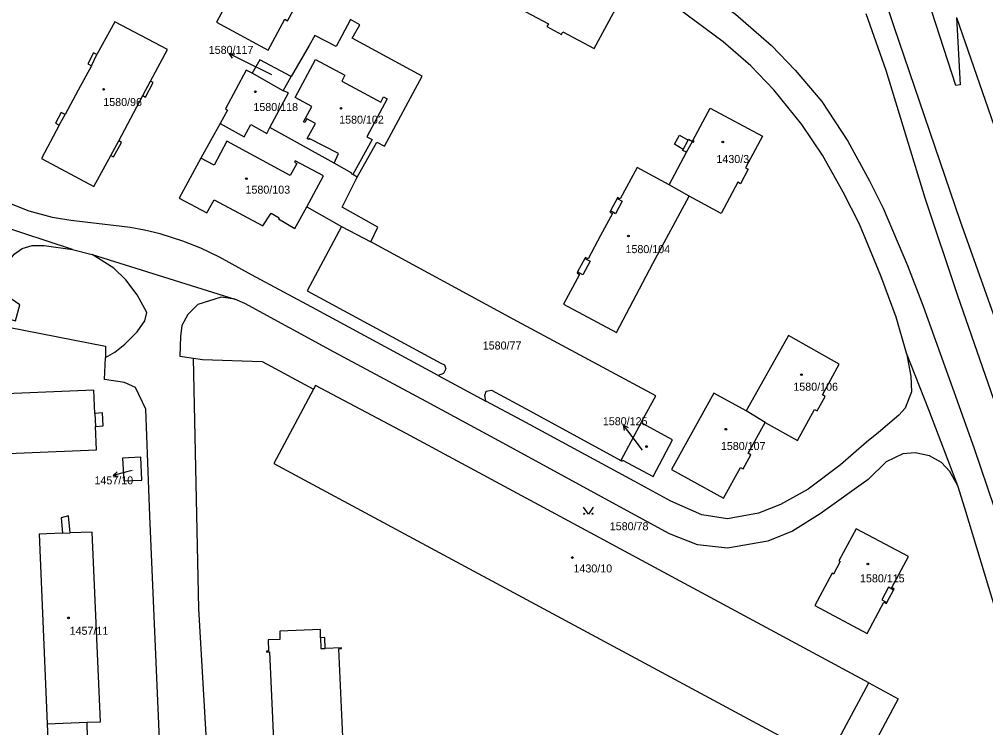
# Model space of a CAD drawing. Extents: x -737240 to -735272, y -1119606 to -1117878.
# Drawn here: x -736070.6 to -735865.3, y -1118481.5 to -1118331.1 of the extents above; entities that cross this region are included whole.
import ezdxf

# ---------------------------------------------------------------- set-up
doc = ezdxf.new("R2010")
doc.units = 0
for name, color, linetype in [('Level 1', 7, 'Continuous'), ('Level 16', 7, 'Continuous'), ('Level 18', 7, 'Continuous'), ('Level 19', 7, 'Continuous'), ('Level 25', 7, 'Continuous'), ('Level 4', 7, 'Continuous')]:
    doc.layers.add(name, color=color, linetype=linetype)

msp = doc.modelspace()

# ---------------------------------------------------------------- linework, layer by layer
at = {"layer": 'Level 1'}
for p, q in [((-735871.5, -1118330.76), (-735863.57, -1118353.56)), ((-736014.55, -1118346.3), (-736021.15, -1118342.55)), ((-736014.55, -1118346.3), (-736012.85, -1118343.25)), ((-736027.93, -1118353.21), (-736032.05, -1118360.56)), ((-736003.75, -1118361.65), (-736017.37, -1118354.1)), ((-735932.57, -1118366.22), (-735928.88, -1118359.35)), ((-735998.8, -1118364.6), (-735999.77, -1118364.06)), ((-735928.33, -1118368.63), (-735932.57, -1118366.22)), ((-735943.62, -1118369.13), (-735945.03, -1118371.81)), ((-736009.55, -1118370.95), (-736002.16, -1118375.09)), ((-736059.31, -1118379.99), (-736081.16, -1118372.84)), ((-736002.16, -1118375.09), (-735995.92, -1118378.38)), ((-736059.31, -1118379.99), (-736055.13, -1118381.03)), ((-736055.13, -1118381.03), (-736024.84, -1118390.55)), ((-735950.45, -1118381.87), (-735951.99, -1118384.74)), ((-735981.63, -1118406.73), (-735971.52, -1118412.19)), ((-735912.15, -1118416.72), (-735916.21, -1118414.23)), ((-735938.42, -1118416.56), (-735942.8, -1118424.77)), ((-735886.28, -1118454.95), (-735884.86, -1118452.29))]:
    msp.add_line(p, q, dxfattribs=at)
for points in [[(-736132.41, -1118173.31), (-735949.71, -1118307.16), (-735930.63, -1118321.15), (-735918.49, -1118330.04), (-735910.8, -1118336.7), (-735905.76, -1118341.88), (-735900.15, -1118348.58), (-735894.58, -1118356.95), (-735890.02, -1118365.43), (-735887.12, -1118371.18), (-735881.94, -1118383.37), (-735878.62, -1118392.03), (-735872.34, -1118409.36), (-735867.8, -1118422.01), (-735863.53, -1118434.8)], [(-735882.16, -1118401.98), (-735884.31, -1118394.32), (-735887.57, -1118385.55), (-735892.14, -1118374.64), (-735895.59, -1118367.84), (-735899.94, -1118359.98), (-735904.37, -1118353.42), (-735910.3, -1118346.1), (-735915.18, -1118341), (-735921.08, -1118335.86), (-735934.46, -1118325.93), (-735953.53, -1118311.86), (-735987.19, -1118287.78), (-736042.03, -1118247.22)], [(-735963.03, -1118329.52), (-735958.22, -1118332.09), (-735958.53, -1118332.66), (-735955.44, -1118334.31), (-735955.14, -1118333.74), (-735948.48, -1118337.3), (-735942.52, -1118326.26), (-735949.37, -1118322.57), (-735949.51, -1118322.82), (-735952.2, -1118321.36), (-735952.07, -1118321.11), (-735957.07, -1118318.42), (-735962.08, -1118315.73), (-735962.21, -1118315.97), (-735964.86, -1118314.54), (-735964.73, -1118314.3), (-735971.6, -1118310.59), (-735977.6, -1118321.72), (-735970.93, -1118325.29), (-735971.25, -1118325.88), (-735968.16, -1118327.53), (-735967.84, -1118326.94), (-735963.03, -1118329.52)], [(-736024.98, -1118324.72), (-736028.73, -1118331.75), (-736017.77, -1118337.69), (-736014.2, -1118331.09)], [(-736014.2, -1118331.09), (-736013.61, -1118331.41), (-736011.95, -1118328.34), (-736012.51, -1118328.04)], [(-735890.77, -1118329.85), (-735886.52, -1118341.93), (-735878.2, -1118368.98), (-735871.31, -1118389.76), (-735858.97, -1118425.18), (-735845.83, -1118463.37)], [(-736042.72, -1118344.22), (-736039.16, -1118337.53), (-736050.34, -1118331.61), (-736054.14, -1118338.61)], [(-735998.8, -1118364.6), (-735994.62, -1118357.18), (-735993.05, -1118358.05), (-735985, -1118343.15), (-735999.87, -1118335.12), (-735998.28, -1118332.29), (-736000.23, -1118331.14), (-736003.3, -1118336.9), (-736007.84, -1118334.58), (-736009.02, -1118336.69), (-736012.85, -1118343.25)], [(-736054.14, -1118338.61), (-736054.82, -1118338.24), (-736056.07, -1118340.55), (-736055.28, -1118340.98)], [(-736012.85, -1118343.25), (-736019.5, -1118339.7), (-736021.15, -1118342.55)], [(-736055.28, -1118340.98), (-736058.09, -1118346.17), (-736060.88, -1118351.32)], [(-736021.15, -1118342.55), (-736022.39, -1118341.92), (-736026.83, -1118350.15), (-736026.35, -1118350.4), (-736027.93, -1118353.21)], [(-736044.37, -1118347.31), (-736043.8, -1118347.62), (-736042.15, -1118344.52), (-736042.72, -1118344.22)], [(-736017.37, -1118354.1), (-736013.45, -1118346.74), (-736014.55, -1118346.3)], [(-736049.5, -1118356.94), (-736046.93, -1118352.11), (-736044.37, -1118347.31)], [(-735927.62, -1118357.03), (-735927.36, -1118357.17), (-735927.26, -1118356.99), (-735927.53, -1118356.85), (-735923.83, -1118349.99), (-735912.73, -1118355.93), (-735916.3, -1118362.62), (-735915.74, -1118362.92), (-735917.39, -1118366.01), (-735917.96, -1118365.71), (-735921.51, -1118372.36), (-735928.33, -1118368.63)], [(-736060.88, -1118351.32), (-736061.7, -1118350.87), (-736062.91, -1118353.18), (-736062.11, -1118353.62)], [(-736062.11, -1118353.62), (-736065.9, -1118360.63), (-736054.75, -1118366.64), (-736051.15, -1118360.04)], [(-736027.93, -1118353.21), (-736022.86, -1118356.06), (-736021.39, -1118353.44), (-736018.03, -1118355.32), (-736017.37, -1118354.1)], [(-735929.58, -1118358.75), (-735931.43, -1118357.61), (-735930.39, -1118355.72), (-735928.5, -1118356.74)], [(-735928.5, -1118356.74), (-735928.42, -1118356.59), (-735927.62, -1118357.03)], [(-736051.15, -1118360.04), (-736050.58, -1118360.34), (-736048.93, -1118357.25), (-736049.5, -1118356.94)], [(-735928.88, -1118359.35), (-735929.67, -1118358.93), (-735929.58, -1118358.75)], [(-736032.05, -1118360.56), (-736036.68, -1118369.1), (-736030.75, -1118372.23), (-736029.23, -1118369.42), (-736018.86, -1118374.99), (-736017.09, -1118372.24), (-736015.39, -1118373.23), (-736015.53, -1118373.48), (-736012.05, -1118375.5), (-736009.55, -1118370.95)], [(-735999.77, -1118364.06), (-736000.05, -1118363.9), (-735999.97, -1118363.76), (-736003.75, -1118361.65)], [(-735932.57, -1118366.22), (-735939.34, -1118362.57), (-735942.93, -1118369.22), (-735943.5, -1118368.91), (-735943.62, -1118369.13)], [(-735995.92, -1118378.38), (-735994.45, -1118375.26), (-736001.99, -1118370.98), (-735998.8, -1118364.6)], [(-735951.99, -1118384.74), (-735952.12, -1118384.97), (-735951.57, -1118385.26), (-735954.98, -1118391.58), (-735943.77, -1118397.62), (-735936, -1118382.98), (-735928.33, -1118368.63)], [(-736210.35, -1118369.86), (-736124.09, -1118377.65), (-736118.86, -1118378.12), (-736090.36, -1118393.09), (-736052.32, -1118400.48), (-736052.29, -1118402.89)], [(-735981.63, -1118406.73), (-736007.57, -1118392.76), (-736021.29, -1118385.4), (-736028.1, -1118381.59), (-736032.04, -1118379.73), (-736035.9, -1118378.2), (-736040.7, -1118376.65), (-736044.01, -1118375.88), (-736047.06, -1118375.3), (-736050.57, -1118374.86), (-736059.63, -1118373.8), (-736063.58, -1118373.19), (-736068.55, -1118371.85), (-736072.64, -1118370.2)], [(-735945.03, -1118371.81), (-735945.15, -1118372.03), (-735944.6, -1118372.33), (-735947.11, -1118376.99), (-735949.78, -1118381.95), (-735950.33, -1118381.65), (-735950.45, -1118381.87)], [(-736002.16, -1118375.09), (-736009.45, -1118388.75), (-735981.08, -1118404.09), (-735980.26, -1118404.51), (-735979.97, -1118405.34), (-735980.5, -1118406.29), (-735981.63, -1118406.73)], [(-736088.43, -1118390.14), (-736071.45, -1118395.11), (-736070.47, -1118391.75), (-736072.34, -1118390.47), (-736073.5, -1118388.55), (-736073.92, -1118386.61), (-736073.71, -1118384.56), (-736072.98, -1118382.66), (-736071.67, -1118380.97), (-736070.03, -1118379.76), (-736067.91, -1118379.12), (-736065.33, -1118379.12), (-736059.31, -1118379.99)], [(-735938.42, -1118416.56), (-735935.38, -1118411.03), (-735965.68, -1118394.77), (-735995.92, -1118378.38)], [(-736052.29, -1118402.89), (-736050.29, -1118401.81), (-736048.17, -1118400.11), (-736045.58, -1118397.49), (-736043.97, -1118395.14), (-736043.55, -1118393.33), (-736045.54, -1118389.63), (-736048, -1118386.46), (-736050.54, -1118383.93), (-736055.13, -1118381.03)], [(-736024.84, -1118390.55), (-736027.76, -1118390.11), (-736032.71, -1118391.67), (-736034.82, -1118393.76), (-736036.07, -1118396.14), (-736036.38, -1118398.46), (-736036.53, -1118402.65), (-736033.57, -1118403.05)], [(-735871.23, -1118430.17), (-735872.91, -1118427.1), (-735874.66, -1118425.19), (-735877.27, -1118423.78), (-735880.27, -1118423.15), (-735882.91, -1118423.39), (-735886.43, -1118425.09), (-735890.27, -1118428.85), (-735900.5, -1118436.1), (-735906.38, -1118439.79), (-735911.6, -1118441.91), (-735920.16, -1118443.4), (-735926.5, -1118442.69), (-735932.48, -1118440.36), (-735943.02, -1118434.61), (-735967.03, -1118421.55), (-735984.18, -1118412.24), (-736003.72, -1118401.79), (-736022.72, -1118391.46), (-736024.84, -1118390.55)], [(-735912.15, -1118416.72), (-735905.32, -1118420.51), (-735901.64, -1118413.93), (-735901.08, -1118414.24), (-735899.38, -1118411.19), (-735899.94, -1118410.88), (-735896.4, -1118404.3), (-735907.23, -1118398.22), (-735916.21, -1118414.23)], [(-735882.16, -1118401.98), (-735881.18, -1118406.91), (-735881.08, -1118410.2), (-735882.38, -1118413.71), (-735883.73, -1118415.14), (-735888.07, -1118418.86), (-735890.64, -1118420.89), (-735896.12, -1118425.69), (-735903.05, -1118430.91), (-735908.92, -1118434.15), (-735913.59, -1118435.98), (-735920.18, -1118437.2), (-735925.64, -1118436.33), (-735932.17, -1118433.45), (-735940, -1118429.21), (-735963.76, -1118416.3), (-735971.52, -1118412.19)], [(-735871.23, -1118430.17), (-735877.42, -1118414.05), (-735882.16, -1118401.98)], [(-736038.55, -1118536.42), (-736042.87, -1118436.57), (-736043.72, -1118413.88), (-736045.95, -1118409.28), (-736048.25, -1118408.23), (-736052.52, -1118407.59), (-736052.29, -1118402.89)], [(-736033.57, -1118403.05), (-736031.67, -1118403.31), (-736019.04, -1118403.8), (-736008.14, -1118409.65)], [(-736022.3, -1118670.45), (-736022.74, -1118659.75), (-736029.23, -1118512.27), (-736032.47, -1118456.28), (-736033.57, -1118403.05)], [(-736054.56, -1118414.79), (-736054.76, -1118409.87), (-736097.43, -1118411.63), (-736096.98, -1118424.31), (-736054.24, -1118422.54), (-736054.44, -1118417.58)], [(-736008.14, -1118409.65), (-736016.57, -1118425.44), (-735899.02, -1118488.63), (-735890.15, -1118471.99)], [(-735890.15, -1118471.99), (-735988.45, -1118419.05), (-736007.65, -1118408.84), (-736008.14, -1118409.65)], [(-735971.52, -1118412.19), (-735971.74, -1118410.99), (-735971.44, -1118410.1), (-735970.28, -1118409.83), (-735962.16, -1118414.22), (-735942.8, -1118424.77)], [(-735916.21, -1118414.23), (-735923.09, -1118410.46), (-735932.06, -1118426.68), (-735921.03, -1118432.8), (-735917.42, -1118426.26), (-735916.85, -1118426.57), (-735915.18, -1118423.58), (-735915.76, -1118423.26), (-735912.15, -1118416.72)], [(-736054.44, -1118417.58), (-736052.82, -1118417.43), (-736052.93, -1118414.66), (-736054.56, -1118414.79)], [(-735942.8, -1118424.77), (-735942.57, -1118424.96), (-735942.43, -1118424.7), (-735935.94, -1118428.19), (-735931.81, -1118420.43), (-735938.21, -1118416.92), (-735938.11, -1118416.7), (-735938.42, -1118416.56)], [(-736044.55, -1118428.99), (-736044.76, -1118424.06), (-736048.66, -1118424.27), (-736048.4, -1118429.12), (-736044.55, -1118428.99)], [(-735817.69, -1118742.18), (-735838.65, -1118677.82), (-735864.4, -1118599.8), (-735860.8, -1118595.54), (-735864.62, -1118583.48), (-735866.55, -1118565.64), (-735866.3, -1118553.11), (-735865.89, -1118546.23), (-735864.43, -1118537.4), (-735858.48, -1118504.53), (-735856.26, -1118491.41), (-735855.98, -1118485.53), (-735857.33, -1118477.46), (-735863.02, -1118457.13), (-735869.75, -1118434.93), (-735871.23, -1118430.17)], [(-736059.79, -1118440.18), (-736060.13, -1118436.56), (-736061.69, -1118436.94), (-736061.43, -1118440.24)], [(-736061.43, -1118440.24), (-736066.37, -1118440.43), (-736064.7, -1118480.68)], [(-736056.21, -1118480.36), (-736053.39, -1118480.25), (-736055.12, -1118440), (-736059.79, -1118440.18)], [(-735884.86, -1118452.29), (-735884.72, -1118452.08), (-735885.28, -1118451.78), (-735881.73, -1118445.15), (-735892.82, -1118439.27), (-735896.5, -1118446.09), (-735896.24, -1118446.23), (-735897.67, -1118448.89), (-735897.93, -1118448.74), (-735901.62, -1118455.57), (-735890.49, -1118461.54), (-735886.94, -1118454.88), (-735886.4, -1118455.17), (-735886.28, -1118454.95)], [(-736006.6, -1118462.46), (-736006.65, -1118460.65), (-736015.23, -1118461.05), (-736015.23, -1118462.78), (-736017.75, -1118462.9), (-736017.64, -1118465.24), (-736018.06, -1118465.26), (-736018.05, -1118465.46), (-736017.47, -1118465.43), (-736014.85, -1118523.29), (-736015.43, -1118523.32), (-736015.42, -1118523.52), (-736002, -1118522.91)], [(-736005.66, -1118464.7), (-736005.71, -1118462.4), (-736006.6, -1118462.46)], [(-736000.11, -1118522.38), (-736002.72, -1118464.77), (-736002.14, -1118464.74), (-736002.15, -1118464.54), (-736005.66, -1118464.7)], [(-735890.15, -1118471.99), (-735883.87, -1118475.37), (-735897.79, -1118501.36), (-735878.46, -1118511.7), (-735870.93, -1118515.72), (-735873.83, -1118533.49), (-735876.75, -1118551.39), (-735867.45, -1118594.32), (-735865.86, -1118601.75), (-735865.22, -1118603.67), (-735840.68, -1118678.71), (-735844.27, -1118679.88), (-735823.87, -1118742.05)], [(-736064.7, -1118480.68), (-736064.56, -1118484.05), (-736056.1, -1118483.69), (-736056.21, -1118480.36)]]:
    msp.add_lwpolyline(points, dxfattribs=at)
at = {"layer": 'Level 16'}
for points in [[(-736025.285, -1118339.336), (-736025.962, -1118338.446), (-736024.844, -1118338.439)], [(-736016.97, -1118342.87), (-736023.27, -1118339.77), (-736025.962, -1118338.446)], [(-735938.21, -1118422.56), (-735940.42, -1118419.68), (-735942.245, -1118417.299)], [(-735942.033, -1118418.396), (-735942.245, -1118417.299), (-735941.239, -1118417.788)], [(-736046.61, -1118426.89), (-736047.77, -1118427.2), (-736050.672, -1118427.959)], [(-736049.578, -1118428.19), (-736050.672, -1118427.959), (-736049.831, -1118427.223)]]:
    msp.add_lwpolyline(points, dxfattribs=at)
at = {"layer": 'Level 25'}
msp.add_lwpolyline([(-735948.72, -1118434.68), (-735949.72, -1118436.18), (-735950.72, -1118434.68)], dxfattribs=at)
for centre in [(-735950.62, -1118436.08), (-735948.82, -1118436.08)]:
    msp.add_circle(centre, 0.1, dxfattribs=at)
for centre in [(-736052.7, -1118345.97), (-736020.48, -1118346.49), (-736002.28, -1118350.01), (-735921.17, -1118357.17), (-736022.35, -1118364.95), (-735941.21, -1118377.11), (-735904.44, -1118406.55), (-735920.5, -1118418.15), (-735937.36, -1118421.82), (-735953.12, -1118445.4), (-735890.33, -1118446.75), (-736060.18, -1118458.2)]:
    msp.add_ellipse(centre, major_axis=(0.18, 0), ratio=0.9848078, dxfattribs=at)
at = {"layer": 'Level 4'}
for p, q in [((-736055.28, -1118340.98), (-736054.14, -1118338.61)), ((-736044.37, -1118347.31), (-736042.72, -1118344.22)), ((-736062.11, -1118353.62), (-736060.88, -1118351.32)), ((-735929.58, -1118358.75), (-735928.5, -1118356.74)), ((-736051.15, -1118360.04), (-736049.5, -1118356.94)), ((-735928.88, -1118359.35), (-735927.62, -1118357.03)), ((-736054.56, -1118414.79), (-736054.44, -1118417.58)), ((-736061.43, -1118440.24), (-736059.79, -1118440.18)), ((-736064.7, -1118480.68), (-736056.21, -1118480.36))]:
    msp.add_line(p, q, dxfattribs=at)
for points in [[(-735871.5, -1118330.76), (-735870.75, -1118344.99), (-735871.64, -1118345.15), (-735881.09, -1118316.09), (-735888.24, -1118292.52), (-735893.07, -1118273.61), (-735896.25, -1118259.08)], [(-735839.74, -1118462.4), (-735850.81, -1118429.97), (-735859.94, -1118404.04), (-735870.64, -1118374.06), (-735884.74, -1118332.69), (-735890.21, -1118316.17), (-735894.62, -1118301.8), (-735897.92, -1118290.15), (-735900.38, -1118280.22), (-735903.97, -1118264.38)], [(-736003.75, -1118361.65), (-736002.78, -1118359.61), (-736009.04, -1118356.4), (-736009.14, -1118356.6), (-736009.44, -1118356.45), (-736007.71, -1118353.23), (-736009.52, -1118352.25), (-736009.95, -1118353.05), (-736010.26, -1118352.89), (-736008.49, -1118349.59), (-736011.99, -1118347.71), (-736007.67, -1118339.66), (-736001.42, -1118343), (-736002.1, -1118344.26), (-735993.83, -1118348.68), (-735993.22, -1118347.54), (-735992.45, -1118347.96), (-735996.79, -1118356.08), (-735995.62, -1118356.62), (-735999.77, -1118364.06)], [(-736009.55, -1118370.95), (-736006, -1118364.35), (-736011.98, -1118361.14), (-736012.13, -1118361.43), (-736011.65, -1118361.69), (-736013.04, -1118364.26), (-736026.49, -1118356.98), (-736029.23, -1118362.07), (-736032.05, -1118360.56)], [(-735943.62, -1118369.13), (-735942.51, -1118369.73), (-735943.94, -1118372.4), (-735945.03, -1118371.81)], [(-735950.45, -1118381.87), (-735949.35, -1118382.47), (-735950.89, -1118385.33), (-735951.99, -1118384.74)], [(-735884.86, -1118452.29), (-735885.96, -1118451.7), (-735887.38, -1118454.36), (-735886.28, -1118454.95)], [(-736006.6, -1118462.46), (-736006.54, -1118464.74), (-736005.66, -1118464.7)]]:
    msp.add_lwpolyline(points, dxfattribs=at)

# ---------------------------------------------------------------- texts
at = {"layer": 'Level 16'}
for s, p in [('1580/117', (-736030.36, -1118338.45)), ('1580/125', (-735946.64, -1118417.3)), ('1457/10', (-736054.64, -1118429.85))]:
    msp.add_text(s, height=1.7, dxfattribs=at).set_placement(p)
at = {"layer": 'Level 18'}
for s, height, p in [('1580/117', 0.1, (-736016.77, -1118342.87)), ('1580/77', 1.7, (-735972.155, -1118401.22)), ('1457/10', 0.1, (-736046.61, -1118426.89)), ('1580/78', 1.7, (-735945.165, -1118439.6))]:
    msp.add_text(s, height=height, dxfattribs=at).set_placement(p)
at = {"layer": 'Level 19'}
for s, height, p in [('1580/96', 1.7, (-736052.77, -1118349.52)), ('1580/118', 1.7, (-736020.875, -1118350.58)), ('1580/102', 1.7, (-736002.655, -1118353.27)), ('1430/3', 1.7, (-735922.505, -1118361.62)), ('1580/103', 1.7, (-736022.555, -1118368.13)), ('1580/104', 1.7, (-735941.825, -1118380.76)), ('1580/106', 1.7, (-735906.165, -1118409.97)), ('1580/125', 0.1, (-735937.985, -1118422.56)), ('1580/107', 1.7, (-735921.565, -1118422.56)), ('1430/10', 1.7, (-735952.88, -1118448.56)), ('1580/115', 1.7, (-735892.005, -1118450.66)), ('1457/11', 1.7, (-736059.92, -1118461.8))]:
    msp.add_text(s, height=height, dxfattribs=at).set_placement(p)

doc.saveas('drawing.dxf')
